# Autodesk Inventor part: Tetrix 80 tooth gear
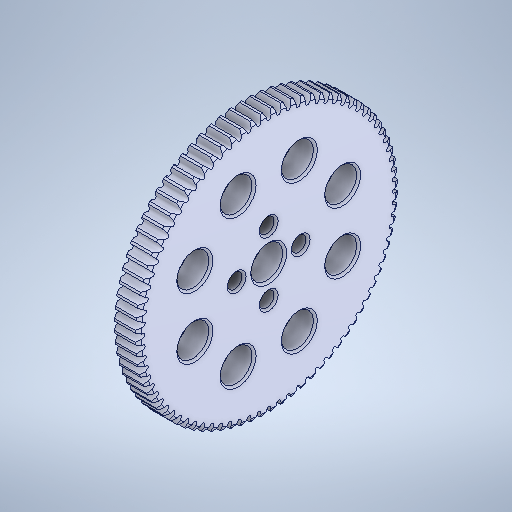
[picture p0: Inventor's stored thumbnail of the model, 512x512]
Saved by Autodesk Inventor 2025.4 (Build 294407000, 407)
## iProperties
Created: 2021-10
Part Number: Tetrix 80 tooth gear
Material: Genérico
Document SubType Name: Modeling
Designer: usuario
Density: 1 g/cm^3
Appearance: Valor por defecto
Author: usuario
Sending System: SolidWorks 2016
Last Author: LENOVO
Last Saved: 2021-10-22
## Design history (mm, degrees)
chamfer "Chamfer2"
node "Sólido1"
